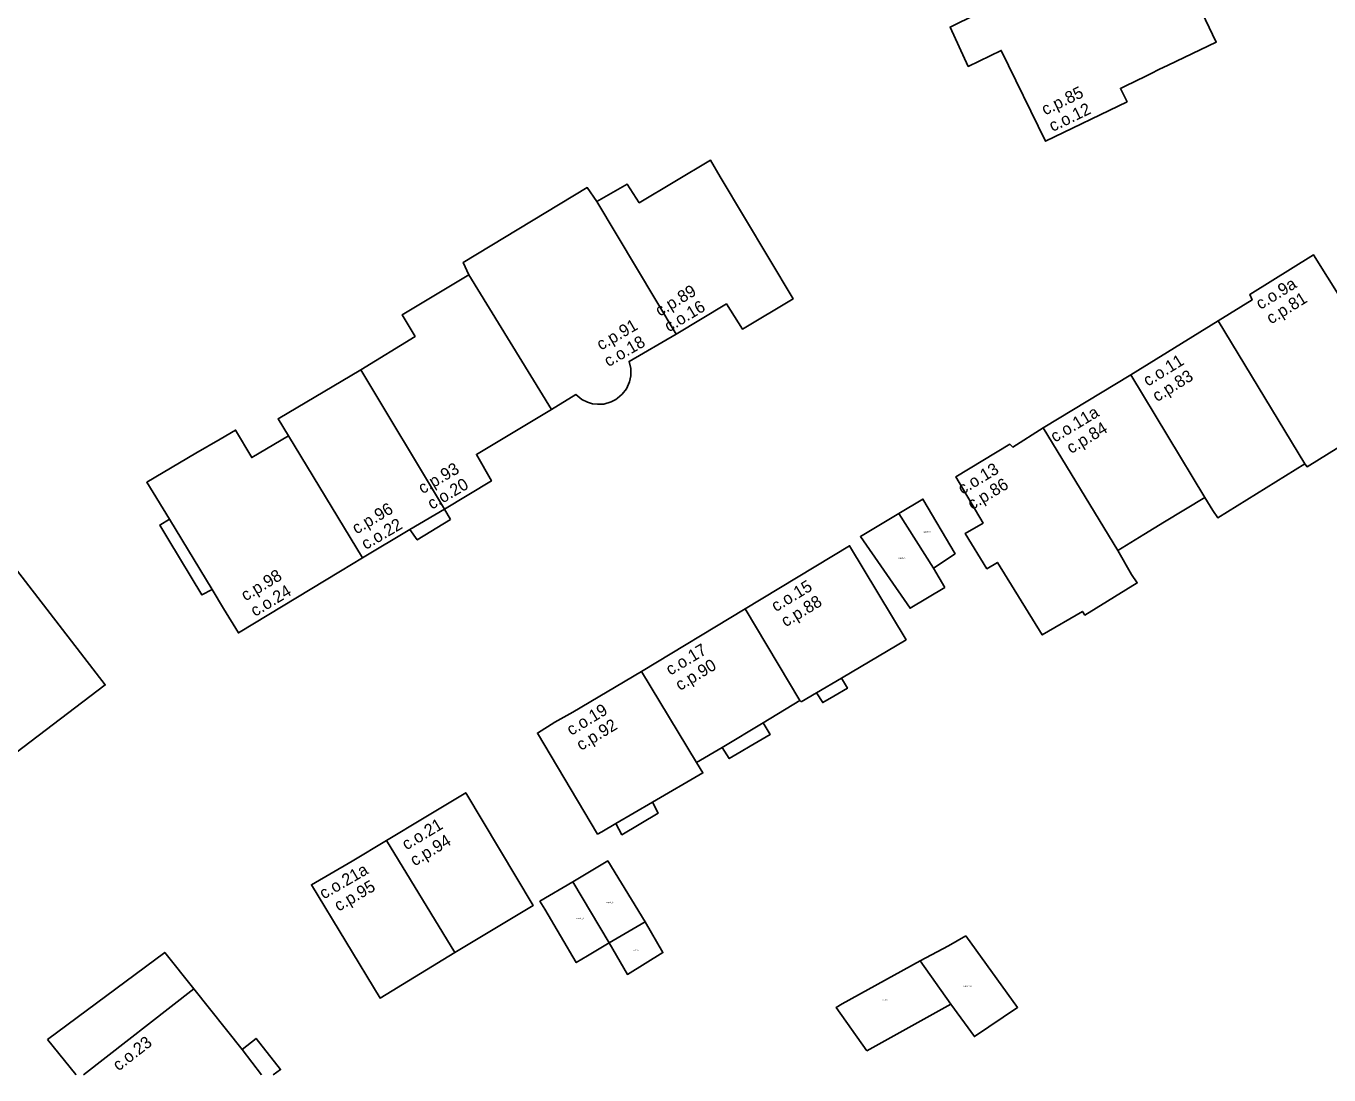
# Model space of a CAD drawing. Extents: x -600391 to -599491, y -1160176 to -1159402.
# Drawn here: x -600144.1 to -600035.9, y -1160176.1 to -1160089 of the extents above; entities that cross this region are included whole.
import ezdxf

# ---------------------------------------------------------------- set-up
doc = ezdxf.new("R2010")
doc.units = 0
for name, color, linetype in [('Level 10', 7, 'Continuous'), ('Level 12', 7, 'Continuous'), ('Level 24', 7, 'Continuous'), ('Level 25', 7, 'Continuous'), ('Level 61', 7, 'Continuous'), ('Level 62', 7, 'Continuous')]:
    doc.layers.add(name, color=color, linetype=linetype)

msp = doc.modelspace()

# ---------------------------------------------------------------- linework, layer by layer
at = {"layer": 'Level 61'}
for p, q in [((-600130.21, -1160168.92), (-600139.38, -1160176.08)), ((-600139.38, -1160176.08), (-600130.21, -1160168.92)), ((-600126.19, -1160173.97), (-600124.58, -1160176.08)), ((-600124.58, -1160176.08), (-600126.19, -1160173.97)), ((-600123, -1160175.64), (-600123.61, -1160176.08)), ((-600139.99, -1160176.08), (-600140.01, -1160176.05))]:
    msp.add_line(p, q, dxfattribs=at)
for points in [[(-600049.69, -1160081.01), (-600045.26, -1160090.3)], [(-600067.38, -1160089.05), (-600066.58, -1160088.67)], [(-600065.86, -1160092.32), (-600067.38, -1160089.05)], [(-600045.26, -1160090.3), (-600049.27, -1160092.22)], [(-600063.13, -1160090.99), (-600065.86, -1160092.32)], [(-600059.45, -1160098.53), (-600063.13, -1160090.99)], [(-600049.27, -1160092.22), (-600050.02, -1160092.59)], [(-600051.12, -1160093.12), (-600052.82, -1160093.95)], [(-600050.67, -1160092.9), (-600051.12, -1160093.12)], [(-600050.02, -1160092.59), (-600050.67, -1160092.9)], [(-600052.82, -1160093.95), (-600053.23, -1160094.15)], [(-600053.23, -1160094.15), (-600052.67, -1160095.26)], [(-600052.67, -1160095.26), (-600059.45, -1160098.53)], [(-600093.2, -1160103.65), (-600087.27, -1160100.11)], [(-600087.27, -1160100.11), (-600086.49, -1160101.48)], [(-600096.71, -1160103.55), (-600094.21, -1160102.1)], [(-600094.21, -1160102.1), (-600093.2, -1160103.65)], [(-600086.49, -1160101.48), (-600080.42, -1160111.63)], [(-600107.84, -1160108.61), (-600097.52, -1160102.39)], [(-600097.52, -1160102.39), (-600096.71, -1160103.55)], [(-600090.14, -1160114.56), (-600096.71, -1160103.55)], [(-600096.71, -1160103.55), (-600090.14, -1160114.56)], [(-600107.35, -1160109.64), (-600107.84, -1160108.61)], [(-600042.47, -1160111.25), (-600037.17, -1160107.97)], [(-600037.17, -1160107.97), (-600034.85, -1160111.68)], [(-600112.9, -1160112.96), (-600107.35, -1160109.64)], [(-600107.35, -1160109.64), (-600100.48, -1160120.82)], [(-600100.48, -1160120.82), (-600107.35, -1160109.64)], [(-600080.42, -1160111.63), (-600084.63, -1160114.14)], [(-600045.09, -1160113.46), (-600042.28, -1160111.71)], [(-600042.28, -1160111.71), (-600042.47, -1160111.25)], [(-600111.82, -1160114.74), (-600112.9, -1160112.96)], [(-600085.96, -1160112.05), (-600090.14, -1160114.56)], [(-600084.63, -1160114.14), (-600085.96, -1160112.05)], [(-600052.35, -1160117.94), (-600045.09, -1160113.46)], [(-600037.91, -1160125.32), (-600045.09, -1160113.46)], [(-600045.09, -1160113.46), (-600037.91, -1160125.32)], [(-600116.33, -1160117.53), (-600111.82, -1160114.74)], [(-600090.14, -1160114.56), (-600094.04, -1160116.82)], [(-600094.04, -1160116.82), (-600093.89, -1160117.4)], [(-600093.89, -1160117.4), (-600093.89, -1160118.02)], [(-600123.2, -1160121.58), (-600116.33, -1160117.53)], [(-600109.39, -1160129.08), (-600116.33, -1160117.53)], [(-600116.33, -1160117.53), (-600109.39, -1160129.08)], [(-600093.89, -1160118.02), (-600094.02, -1160118.53)], [(-600059.65, -1160122.35), (-600052.35, -1160117.94)], [(-600052.35, -1160117.94), (-600046.22, -1160128.13)], [(-600046.22, -1160128.13), (-600052.35, -1160117.94)], [(-600094.62, -1160119.55), (-600095.01, -1160119.88)], [(-600094.27, -1160119.09), (-600094.62, -1160119.55)], [(-600094.02, -1160118.53), (-600094.27, -1160119.09)], [(-600098.48, -1160119.58), (-600100.48, -1160120.82)], [(-600097.97, -1160119.98), (-600098.48, -1160119.58)], [(-600097.51, -1160120.21), (-600097.97, -1160119.98)], [(-600097.08, -1160120.34), (-600097.51, -1160120.21)], [(-600096.68, -1160120.38), (-600097.08, -1160120.34)], [(-600096.15, -1160120.36), (-600096.68, -1160120.38)], [(-600095.52, -1160120.18), (-600096.15, -1160120.36)], [(-600095.15, -1160119.98), (-600095.52, -1160120.18)], [(-600095.01, -1160119.88), (-600095.15, -1160119.98)], [(-600122.34, -1160122.99), (-600123.2, -1160121.58)], [(-600100.48, -1160120.82), (-600106.73, -1160124.54)], [(-600128.03, -1160123.28), (-600126.74, -1160122.53)], [(-600126.74, -1160122.53), (-600125.4, -1160124.81)], [(-600062.15, -1160123.94), (-600059.65, -1160122.35)], [(-600059.65, -1160122.35), (-600053.45, -1160132.53)], [(-600053.45, -1160132.53), (-600059.65, -1160122.35)], [(-600130.03, -1160124.45), (-600128.03, -1160123.28)], [(-600125.4, -1160124.81), (-600122.34, -1160122.99)], [(-600116.18, -1160133.14), (-600122.34, -1160122.99)], [(-600122.34, -1160122.99), (-600116.18, -1160133.14)], [(-600066.89, -1160126.4), (-600062.41, -1160123.7)], [(-600062.41, -1160123.7), (-600062.15, -1160123.94)], [(-600134.11, -1160126.85), (-600130.03, -1160124.45)], [(-600106.73, -1160124.54), (-600105.48, -1160126.74)], [(-600035.08, -1160123.93), (-600037.72, -1160125.57)], [(-600151.58, -1160125.54), (-600137.57, -1160143.69)], [(-600037.91, -1160125.32), (-600045.14, -1160129.8)], [(-600037.72, -1160125.57), (-600037.91, -1160125.32)], [(-600132.24, -1160129.93), (-600134.11, -1160126.85)], [(-600105.48, -1160126.74), (-600109.39, -1160129.08)], [(-600064.64, -1160130.25), (-600066.89, -1160126.4)], [(-600046.22, -1160128.13), (-600049.57, -1160130.15)], [(-600045.55, -1160129.21), (-600046.22, -1160128.13)], [(-600109.39, -1160129.08), (-600112.25, -1160130.79)], [(-600112.25, -1160130.79), (-600109.39, -1160129.08)], [(-600109.39, -1160129.08), (-600108.88, -1160129.94)], [(-600071.62, -1160129.45), (-600069.63, -1160128.26)], [(-600069.63, -1160128.26), (-600066.96, -1160132.8)], [(-600045.14, -1160129.8), (-600045.55, -1160129.21)], [(-600133.03, -1160130.41), (-600132.24, -1160129.93)], [(-600132.24, -1160129.93), (-600128.69, -1160135.77)], [(-600128.69, -1160135.77), (-600132.24, -1160129.93)], [(-600108.88, -1160129.94), (-600111.64, -1160131.64)], [(-600074.83, -1160131.37), (-600071.62, -1160129.45)], [(-600071.62, -1160129.45), (-600068.76, -1160134)], [(-600068.76, -1160134), (-600071.62, -1160129.45)], [(-600066.11, -1160131.11), (-600064.64, -1160130.25)], [(-600049.57, -1160130.15), (-600051.27, -1160131.2)], [(-600132.27, -1160131.67), (-600133.03, -1160130.41)], [(-600112.25, -1160130.79), (-600116.18, -1160133.14)], [(-600111.64, -1160131.64), (-600112.25, -1160130.79)], [(-600070.7, -1160137.32), (-600074.83, -1160131.37)], [(-600064.32, -1160134.04), (-600066.11, -1160131.11)], [(-600051.27, -1160131.2), (-600053.45, -1160132.53)], [(-600129.53, -1160136.22), (-600132.27, -1160131.67)], [(-600084.41, -1160137.36), (-600075.73, -1160132.13)], [(-600075.73, -1160132.13), (-600071.03, -1160139.93)], [(-600053.45, -1160132.53), (-600052.3, -1160134.52)], [(-600116.18, -1160133.14), (-600118.01, -1160134.25)], [(-600066.96, -1160132.8), (-600068.76, -1160134)], [(-600063.44, -1160133.52), (-600064.32, -1160134.04)], [(-600059.72, -1160139.54), (-600063.44, -1160133.52)], [(-600118.01, -1160134.25), (-600126.5, -1160139.37)], [(-600068.76, -1160134), (-600067.81, -1160135.59)], [(-600052.3, -1160134.52), (-600051.83, -1160135.21)], [(-600128.69, -1160135.77), (-600129.53, -1160136.22)], [(-600127.73, -1160137.35), (-600128.69, -1160135.77)], [(-600067.81, -1160135.59), (-600070.7, -1160137.32)], [(-600051.83, -1160135.21), (-600056.17, -1160137.89)], [(-600126.5, -1160139.37), (-600127.73, -1160137.35)], [(-600093, -1160142.57), (-600084.41, -1160137.36)], [(-600079.85, -1160144.99), (-600084.41, -1160137.36)], [(-600084.41, -1160137.36), (-600079.85, -1160144.99)], [(-600056.38, -1160137.58), (-600059.72, -1160139.54)], [(-600056.17, -1160137.89), (-600056.38, -1160137.58)], [(-600071.03, -1160139.93), (-600076.41, -1160143.12)], [(-600098.71, -1160145.94), (-600093, -1160142.57)], [(-600093, -1160142.57), (-600088.43, -1160150.14)], [(-600088.43, -1160150.14), (-600093, -1160142.57)], [(-600078.46, -1160144.34), (-600076.41, -1160143.12)], [(-600076.41, -1160143.12), (-600078.46, -1160144.34)], [(-600076.41, -1160143.12), (-600075.91, -1160143.96)], [(-600137.57, -1160143.69), (-600150.59, -1160153.57)], [(-600078.46, -1160144.34), (-600079.74, -1160145.1)], [(-600077.96, -1160145.16), (-600078.46, -1160144.34)], [(-600075.91, -1160143.96), (-600077.04, -1160144.62)], [(-600079.85, -1160144.99), (-600082.91, -1160146.83)], [(-600079.74, -1160145.1), (-600079.85, -1160144.99)], [(-600077.04, -1160144.62), (-600077.96, -1160145.16)], [(-600100.2, -1160146.79), (-600098.71, -1160145.94)], [(-600101.66, -1160147.69), (-600100.2, -1160146.79)], [(-600096.66, -1160156.08), (-600101.66, -1160147.69)], [(-600086.32, -1160148.88), (-600082.91, -1160146.83)], [(-600082.91, -1160146.83), (-600086.32, -1160148.88)], [(-600082.91, -1160146.83), (-600082.32, -1160147.8)], [(-600083.99, -1160148.78), (-600084.72, -1160149.22)], [(-600082.32, -1160147.8), (-600083.99, -1160148.78)], [(-600086.32, -1160148.88), (-600088.43, -1160150.14)], [(-600085.72, -1160149.8), (-600086.32, -1160148.88)], [(-600084.72, -1160149.22), (-600085.72, -1160149.8)], [(-600088.43, -1160150.14), (-600087.91, -1160150.99)], [(-600087.91, -1160150.99), (-600092.1, -1160153.43)], [(-600111.08, -1160154.73), (-600107.61, -1160152.65)], [(-600107.61, -1160152.65), (-600102.02, -1160162.01)], [(-600092.1, -1160153.43), (-600095.14, -1160155.2)], [(-600095.14, -1160155.2), (-600092.1, -1160153.43)], [(-600092.1, -1160153.43), (-600091.64, -1160154.35)], [(-600114.19, -1160156.6), (-600111.08, -1160154.73)], [(-600095.14, -1160155.2), (-600096.3, -1160155.88)], [(-600094.64, -1160156.13), (-600095.14, -1160155.2)], [(-600091.64, -1160154.35), (-600094.64, -1160156.13)], [(-600096.3, -1160155.88), (-600096.66, -1160156.08)], [(-600117.06, -1160158.33), (-600114.19, -1160156.6)], [(-600114.19, -1160156.6), (-600108.52, -1160165.9)], [(-600108.52, -1160165.9), (-600114.19, -1160156.6)], [(-600120.43, -1160160.29), (-600117.06, -1160158.33)], [(-600098.72, -1160160.04), (-600095.81, -1160158.31)], [(-600095.81, -1160158.31), (-600092.71, -1160163.35)], [(-600114.73, -1160169.7), (-600120.43, -1160160.29)], [(-600101.45, -1160161.66), (-600098.72, -1160160.04)], [(-600095.71, -1160165.11), (-600098.72, -1160160.04)], [(-600098.72, -1160160.04), (-600095.71, -1160165.11)], [(-600101.05, -1160162.32), (-600101.45, -1160161.66)], [(-600102.02, -1160162.01), (-600108.52, -1160165.9)], [(-600098.43, -1160166.75), (-600101.05, -1160162.32)], [(-600092.71, -1160163.35), (-600095.71, -1160165.11)], [(-600095.71, -1160165.11), (-600092.71, -1160163.35)], [(-600092.71, -1160163.35), (-600091.23, -1160165.92)], [(-600067.52, -1160165.35), (-600066.06, -1160164.53)], [(-600066.06, -1160164.53), (-600061.77, -1160170.47)], [(-600142.37, -1160173.13), (-600132.62, -1160165.91)], [(-600132.62, -1160165.91), (-600130.21, -1160168.92)], [(-600108.52, -1160165.9), (-600114.73, -1160169.7)], [(-600095.71, -1160165.11), (-600097.5, -1160166.2)], [(-600094.18, -1160167.73), (-600095.71, -1160165.11)], [(-600091.23, -1160165.92), (-600094.18, -1160167.73)], [(-600069.86, -1160166.6), (-600067.52, -1160165.35)], [(-600097.5, -1160166.2), (-600098.43, -1160166.75)], [(-600076.34, -1160170.18), (-600069.86, -1160166.6)], [(-600069.86, -1160166.6), (-600067.31, -1160170.21)], [(-600067.31, -1160170.21), (-600069.86, -1160166.6)], [(-600130.21, -1160168.92), (-600126.19, -1160173.97)], [(-600076.85, -1160170.48), (-600076.34, -1160170.18)], [(-600067.31, -1160170.21), (-600074.29, -1160174.07)], [(-600065.36, -1160172.89), (-600067.31, -1160170.21)], [(-600074.29, -1160174.07), (-600076.85, -1160170.48)], [(-600061.77, -1160170.47), (-600065.36, -1160172.89)], [(-600140.01, -1160176.05), (-600142.37, -1160173.13)], [(-600126.19, -1160173.97), (-600125.03, -1160173.05)], [(-600125.03, -1160173.05), (-600123, -1160175.64)]]:
    msp.add_lwpolyline(points, dxfattribs=at)
at = {"layer": 'Level 62'}
for p, q in [((-600126.19, -1160173.97), (-600124.58, -1160176.08)), ((-600124.58, -1160176.08), (-600126.19, -1160173.97))]:
    msp.add_line(p, q, dxfattribs=at)
for points in [[(-600050.02, -1160092.59), (-600050.67, -1160092.9), (-600051.12, -1160093.12), (-600052.82, -1160093.95), (-600053.23, -1160094.15), (-600052.67, -1160095.26), (-600059.45, -1160098.53), (-600063.13, -1160090.99), (-600065.86, -1160092.32), (-600067.38, -1160089.05), (-600066.58, -1160088.67), (-600065.37, -1160088.09), (-600060.91, -1160085.95), (-600049.84, -1160080.67), (-600049.69, -1160081.01), (-600045.26, -1160090.3), (-600049.27, -1160092.22), (-600050.02, -1160092.59)], [(-600096.71, -1160103.55), (-600094.21, -1160102.1), (-600093.2, -1160103.65), (-600087.27, -1160100.11), (-600086.49, -1160101.48), (-600080.42, -1160111.63), (-600084.63, -1160114.14), (-600085.96, -1160112.05), (-600090.14, -1160114.56), (-600096.71, -1160103.55)], [(-600100.48, -1160120.82), (-600107.35, -1160109.64), (-600107.84, -1160108.61), (-600097.52, -1160102.39), (-600096.71, -1160103.55), (-600090.14, -1160114.56), (-600094.04, -1160116.82), (-600093.89, -1160117.4), (-600093.89, -1160118.02), (-600094.02, -1160118.53), (-600094.27, -1160119.09), (-600094.62, -1160119.55), (-600095.01, -1160119.88), (-600095.15, -1160119.98), (-600095.52, -1160120.18), (-600096.15, -1160120.36), (-600096.68, -1160120.38), (-600097.08, -1160120.34), (-600097.51, -1160120.21), (-600097.97, -1160119.98), (-600098.48, -1160119.58), (-600100.48, -1160120.82)], [(-600033.41, -1160126.61), (-600035.08, -1160123.93), (-600037.72, -1160125.57), (-600037.91, -1160125.32), (-600045.09, -1160113.46), (-600042.28, -1160111.71), (-600042.47, -1160111.25), (-600037.17, -1160107.97), (-600034.85, -1160111.68), (-600034.04, -1160113.09), (-600033.3, -1160112.66), (-600028.97, -1160120.19), (-600029.48, -1160120.52), (-600027.87, -1160123.2), (-600028.93, -1160123.93), (-600027.79, -1160125.78), (-600031.07, -1160127.85), (-600031.57, -1160126.99), (-600032.2, -1160125.89), (-600033.41, -1160126.61)], [(-600116.33, -1160117.53), (-600111.82, -1160114.74), (-600112.9, -1160112.96), (-600107.35, -1160109.64), (-600100.48, -1160120.82), (-600106.73, -1160124.54), (-600105.48, -1160126.74), (-600109.39, -1160129.08), (-600116.33, -1160117.53)], [(-600045.09, -1160113.46), (-600037.91, -1160125.32), (-600045.14, -1160129.8), (-600045.55, -1160129.21), (-600046.22, -1160128.13), (-600052.35, -1160117.94), (-600045.09, -1160113.46)], [(-600116.33, -1160117.53), (-600109.39, -1160129.08), (-600112.25, -1160130.79), (-600116.18, -1160133.14), (-600122.34, -1160122.99), (-600123.2, -1160121.58), (-600116.33, -1160117.53)], [(-600059.65, -1160122.35), (-600052.35, -1160117.94), (-600046.22, -1160128.13), (-600049.57, -1160130.15), (-600051.27, -1160131.2), (-600053.45, -1160132.53), (-600059.65, -1160122.35)], [(-600127.73, -1160137.35), (-600128.69, -1160135.77), (-600132.24, -1160129.93), (-600134.11, -1160126.85), (-600130.03, -1160124.45), (-600128.03, -1160123.28), (-600126.74, -1160122.53), (-600125.4, -1160124.81), (-600122.34, -1160122.99), (-600116.18, -1160133.14), (-600118.01, -1160134.25), (-600126.5, -1160139.37), (-600127.73, -1160137.35)], [(-600059.65, -1160122.35), (-600053.45, -1160132.53), (-600052.3, -1160134.52), (-600051.83, -1160135.21), (-600056.17, -1160137.89), (-600056.38, -1160137.58), (-600059.72, -1160139.54), (-600063.44, -1160133.52), (-600064.32, -1160134.04), (-600066.11, -1160131.11), (-600064.64, -1160130.25), (-600066.89, -1160126.4), (-600062.41, -1160123.7), (-600062.15, -1160123.94), (-600059.65, -1160122.35)], [(-600155.79, -1160126.72), (-600154.49, -1160125.71), (-600152.56, -1160124.27), (-600151.58, -1160125.54), (-600137.57, -1160143.69), (-600150.59, -1160153.57), (-600152.93, -1160155.35), (-600156.14, -1160157.79), (-600158.95, -1160154.26), (-600159.75, -1160153.24), (-600160.25, -1160152.62), (-600159.94, -1160152.37), (-600170.41, -1160138.74), (-600166.52, -1160135.6), (-600167.09, -1160134.9), (-600165.88, -1160133.93), (-600155.79, -1160126.72)], [(-600108.88, -1160129.94), (-600111.64, -1160131.64), (-600112.25, -1160130.79), (-600109.39, -1160129.08), (-600108.88, -1160129.94)], [(-600068.76, -1160134), (-600071.62, -1160129.45), (-600069.63, -1160128.26), (-600066.96, -1160132.8), (-600068.76, -1160134)], [(-600132.24, -1160129.93), (-600128.69, -1160135.77), (-600129.53, -1160136.22), (-600132.27, -1160131.67), (-600133.03, -1160130.41), (-600132.24, -1160129.93)], [(-600067.81, -1160135.59), (-600070.7, -1160137.32), (-600074.83, -1160131.37), (-600071.62, -1160129.45), (-600068.76, -1160134), (-600067.81, -1160135.59)], [(-600079.74, -1160145.1), (-600079.85, -1160144.99), (-600084.41, -1160137.36), (-600075.73, -1160132.13), (-600071.03, -1160139.93), (-600076.41, -1160143.12), (-600078.46, -1160144.34), (-600079.74, -1160145.1)], [(-600086.32, -1160148.88), (-600088.43, -1160150.14), (-600093, -1160142.57), (-600084.41, -1160137.36), (-600079.85, -1160144.99), (-600082.91, -1160146.83), (-600086.32, -1160148.88)], [(-600093, -1160142.57), (-600088.43, -1160150.14), (-600087.91, -1160150.99), (-600092.1, -1160153.43), (-600095.14, -1160155.2), (-600096.3, -1160155.88), (-600096.66, -1160156.08), (-600101.66, -1160147.69), (-600100.2, -1160146.79), (-600098.71, -1160145.94), (-600093, -1160142.57)], [(-600078.46, -1160144.34), (-600076.41, -1160143.12), (-600075.91, -1160143.96), (-600077.04, -1160144.62), (-600077.96, -1160145.16), (-600078.46, -1160144.34)], [(-600084.72, -1160149.22), (-600085.72, -1160149.8), (-600086.32, -1160148.88), (-600082.91, -1160146.83), (-600082.32, -1160147.8), (-600083.99, -1160148.78), (-600084.72, -1160149.22)], [(-600114.19, -1160156.6), (-600111.08, -1160154.73), (-600107.61, -1160152.65), (-600102.02, -1160162.01), (-600108.52, -1160165.9), (-600114.19, -1160156.6)], [(-600095.14, -1160155.2), (-600092.1, -1160153.43), (-600091.64, -1160154.35), (-600094.64, -1160156.13), (-600095.14, -1160155.2)], [(-600117.06, -1160158.33), (-600114.19, -1160156.6), (-600108.52, -1160165.9), (-600114.73, -1160169.7), (-600120.43, -1160160.29), (-600117.06, -1160158.33)], [(-600092.71, -1160163.35), (-600095.71, -1160165.11), (-600098.72, -1160160.04), (-600095.81, -1160158.31), (-600092.71, -1160163.35)], [(-600095.71, -1160165.11), (-600097.5, -1160166.2), (-600098.43, -1160166.75), (-600101.05, -1160162.32), (-600101.45, -1160161.66), (-600098.72, -1160160.04), (-600095.71, -1160165.11)], [(-600092.71, -1160163.35), (-600091.23, -1160165.92), (-600094.18, -1160167.73), (-600095.71, -1160165.11), (-600092.71, -1160163.35)], [(-600066.06, -1160164.53), (-600061.77, -1160170.47), (-600065.36, -1160172.89), (-600067.31, -1160170.21), (-600069.86, -1160166.6), (-600067.52, -1160165.35), (-600066.06, -1160164.53)], [(-600142.37, -1160173.13), (-600132.62, -1160165.91), (-600130.21, -1160168.92), (-600139.38, -1160176.08)], [(-600074.29, -1160174.07), (-600076.85, -1160170.48), (-600076.34, -1160170.18), (-600069.86, -1160166.6), (-600067.31, -1160170.21), (-600074.29, -1160174.07)], [(-600139.38, -1160176.08), (-600130.21, -1160168.92), (-600126.19, -1160173.97)], [(-600139.99, -1160176.08), (-600140.01, -1160176.05), (-600142.37, -1160173.13)], [(-600126.19, -1160173.97), (-600125.03, -1160173.05), (-600123, -1160175.64), (-600123.61, -1160176.08)]]:
    msp.add_lwpolyline(points, dxfattribs=at)

# ---------------------------------------------------------------- texts
at = {"layer": 'Level 10'}
for s, rotation, p in [('c.o.12', 25.6759, (-600058.86, -1160097.77)), ('c.o.9a', 31.7509, (-600041.59, -1160112.55)), ('c.o.16', 30.9844, (-600090.74, -1160114.42)), ('c.o.18', 30.0931, (-600095.76, -1160117.31)), ('c.o.11', 31.6762, (-600050.95, -1160118.93)), ('c.o.11a', 31.1387, (-600058.66, -1160123.58)), ('c.o.13', 31.0768, (-600066.35, -1160127.91)), ('c.o.20', 30.4115, (-600110.43, -1160129.15)), ('c.o.22', 30.5579, (-600115.92, -1160132.49)), ('c.o.24', 31.1053, (-600125.12, -1160138.05)), ('c.o.15', 31.0718, (-600081.85, -1160137.65)), ('c.o.17', 31.005, (-600090.62, -1160142.93)), ('c.o.19', 31.2929, (-600098.85, -1160147.93)), ('c.o.21', 30.9765, (-600112.54, -1160157.44)), ('c.o.21a', 30.1855, (-600119.41, -1160161.52)), ('c.o.23', 37.9896, (-600136.46, -1160175.8))]:
    msp.add_text(s, height=1, rotation=rotation, dxfattribs=at).set_placement(p)
at = {"layer": 'Level 12'}
for s, rotation, p in [('c.p.85', 25.6759, (-600059.48, -1160096.4)), ('c.p.89', 30.9844, (-600091.49, -1160113.12)), ('c.p.81', 31.7509, (-600040.71, -1160113.76)), ('c.p.91', 30.0931, (-600096.38, -1160115.93)), ('c.p.83', 31.6762, (-600050.18, -1160120.21)), ('c.p.84', 31.1387, (-600057.32, -1160124.52)), ('c.p.93', 30.4115, (-600111.2, -1160127.86)), ('c.p.86', 31.0768, (-600065.55, -1160129.18)), ('c.p.96', 30.5579, (-600116.69, -1160131.2)), ('c.p.98', 31.1053, (-600125.91, -1160136.76)), ('c.p.88', 31.0718, (-600081.04, -1160138.91)), ('c.p.90', 31.005, (-600089.82, -1160144.2)), ('c.p.92', 31.2929, (-600098.04, -1160149.18)), ('c.p.94', 30.9765, (-600111.86, -1160158.77)), ('c.p.95', 30.1855, (-600118.18, -1160162.53))]:
    msp.add_text(s, height=1, rotation=rotation, dxfattribs=at).set_placement(p)
at = {"layer": 'Level 24'}
msp.add_text('c.z.333', height=0.1, dxfattribs=at).set_placement((-600073.02, -1160169.88))
at = {"layer": 'Level 25'}
for s, p in [('c.pp.86_A', (-600069.62, -1160131.01)), ('c.pp.88_A', (-600071.72, -1160133.19)), ('c.pp.92_A', (-600095.98, -1160161.79)), ('c.pp.94_A', (-600098.44, -1160163.12)), ('c.pp.92_B', (-600093.87, -1160165.77)), ('c.pp.544_A', (-600066.29, -1160168.74))]:
    msp.add_text(s, height=0.1, dxfattribs=at).set_placement(p)

doc.saveas('drawing.dxf')
